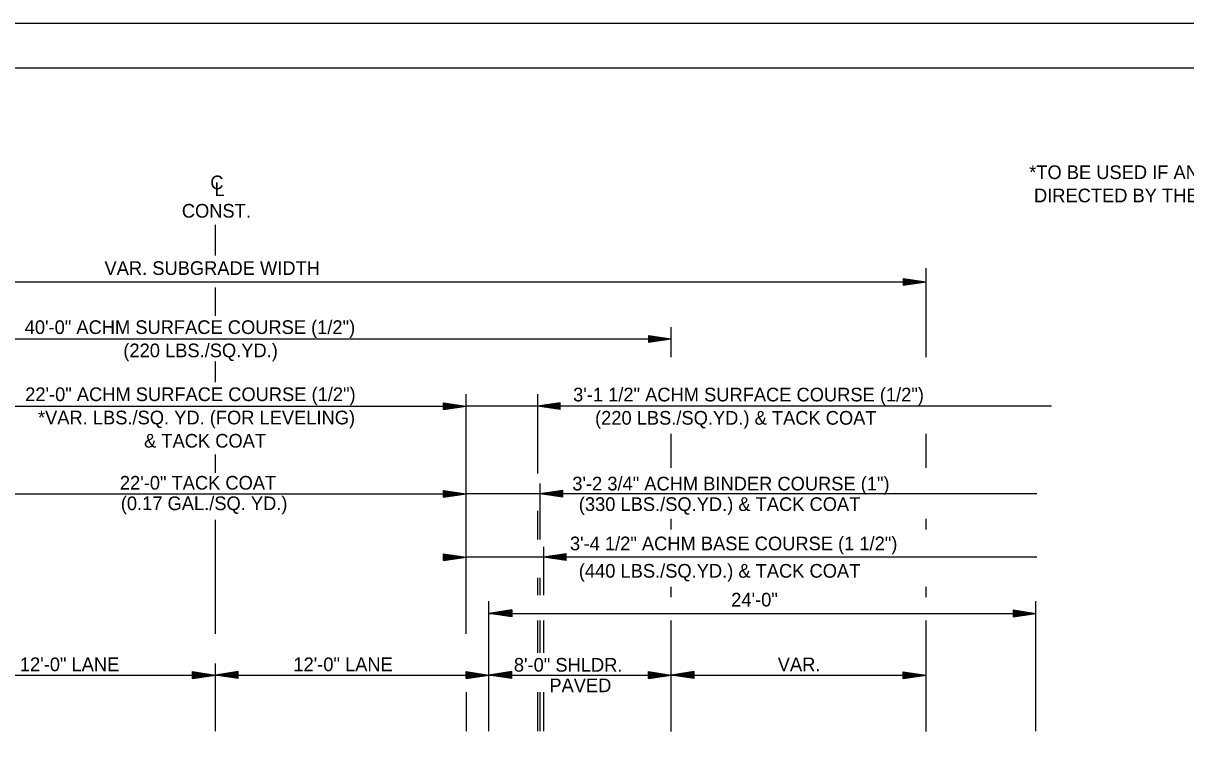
# Model space of a CAD drawing. Extents: x 1371763 to 1372860, y 385599 to 385872.
# Drawn here: x 1372551.5 to 1372602.5, y 385673.9 to 385705.3 of the extents above; entities that cross this region are included whole.
import ezdxf

# ---------------------------------------------------------------- set-up
doc = ezdxf.new("R2010")
doc.units = 0
for name, color, linetype in [('R_Border', 7, 'Continuous'), ('R_Draft', 7, 'Continuous'), ('R_No Plot', 7, 'Continuous')]:
    doc.layers.add(name, color=color, linetype=linetype)

msp = doc.modelspace()

# ---------------------------------------------------------------- linework, layer by layer
at = {"layer": 'R_Border'}
for p, q in [((1372499.208, 385703.307), (1372657.298, 385703.307)), ((1372575.468, 385703.177), (1372575.468, 385703.177)), ((1372575.468, 385703.177), (1372575.468, 385703.177))]:
    msp.add_line(p, q, dxfattribs=at)
at = {"layer": 'R_Draft'}
for p, q in [((1372559.923, 385695.069), (1372559.923, 385696.419)), ((1372591.103, 385690.609), (1372591.103, 385694.519)), ((1372525.346, 385693.919), (1372591.103, 385693.919)), ((1372590.103, 385694.069), (1372591.103, 385693.919)), ((1372590.103, 385694.069), (1372590.103, 385693.769)), ((1372590.103, 385694.044), (1372590.936, 385693.919)), ((1372590.103, 385694.018), (1372590.764, 385693.919)), ((1372590.103, 385693.993), (1372590.598, 385693.919)), ((1372590.103, 385693.967), (1372590.428, 385693.919)), ((1372590.103, 385693.942), (1372590.261, 385693.919)), ((1372590.103, 385693.769), (1372591.103, 385693.919)), ((1372590.103, 385693.87), (1372590.428, 385693.919)), ((1372590.103, 385693.819), (1372590.764, 385693.919)), ((1372590.103, 385693.794), (1372590.936, 385693.919)), ((1372590.103, 385693.844), (1372590.598, 385693.919)), ((1372590.103, 385693.895), (1372590.261, 385693.919)), ((1372559.923, 385692.419), (1372559.923, 385693.669)), ((1372579.918, 385690.609), (1372579.918, 385691.929)), ((1372539.919, 385691.419), (1372579.918, 385691.419)), ((1372578.918, 385691.569), (1372579.918, 385691.419)), ((1372578.918, 385691.569), (1372578.918, 385691.269)), ((1372578.918, 385691.544), (1372579.751, 385691.419)), ((1372578.918, 385691.518), (1372579.579, 385691.419)), ((1372578.918, 385691.493), (1372579.413, 385691.419)), ((1372578.918, 385691.467), (1372579.243, 385691.419)), ((1372578.918, 385691.442), (1372579.076, 385691.419)), ((1372578.918, 385691.269), (1372579.918, 385691.419)), ((1372578.918, 385691.37), (1372579.243, 385691.419)), ((1372578.918, 385691.319), (1372579.579, 385691.419)), ((1372578.918, 385691.294), (1372579.751, 385691.419)), ((1372578.918, 385691.344), (1372579.413, 385691.419)), ((1372578.918, 385691.395), (1372579.076, 385691.419)), ((1372559.923, 385689.51), (1372559.923, 385690.419)), ((1372570.921, 385678.476), (1372570.923, 385688.985)), ((1372574.052, 385688.985), (1372574.052, 385685.506)), ((1372548.923, 385688.463), (1372570.923, 385688.463)), ((1372569.923, 385688.613), (1372570.923, 385688.463)), ((1372569.923, 385688.313), (1372569.923, 385688.613)), ((1372569.923, 385688.588), (1372570.756, 385688.463)), ((1372569.923, 385688.563), (1372570.584, 385688.463)), ((1372569.923, 385688.538), (1372570.417, 385688.463)), ((1372569.923, 385688.512), (1372570.248, 385688.463)), ((1372569.923, 385688.487), (1372570.081, 385688.463)), ((1372569.923, 385688.313), (1372570.923, 385688.463)), ((1372569.923, 385688.415), (1372570.248, 385688.463)), ((1372569.923, 385688.364), (1372570.584, 385688.463)), ((1372569.923, 385688.338), (1372570.756, 385688.463)), ((1372569.923, 385688.389), (1372570.417, 385688.463)), ((1372569.923, 385688.44), (1372570.081, 385688.463)), ((1372596.599, 385688.463), (1372570.923, 385688.463)), ((1372575.052, 385688.613), (1372574.052, 385688.463)), ((1372575.052, 385688.313), (1372574.052, 385688.463)), ((1372575.052, 385688.588), (1372574.219, 385688.463)), ((1372575.052, 385688.338), (1372574.219, 385688.463)), ((1372575.052, 385688.563), (1372574.391, 385688.463)), ((1372575.052, 385688.364), (1372574.391, 385688.463)), ((1372575.052, 385688.538), (1372574.558, 385688.463)), ((1372575.052, 385688.389), (1372574.558, 385688.463)), ((1372575.052, 385688.512), (1372574.727, 385688.463)), ((1372575.052, 385688.415), (1372574.727, 385688.463)), ((1372575.052, 385688.487), (1372574.894, 385688.463)), ((1372575.052, 385688.44), (1372574.894, 385688.463)), ((1372575.052, 385688.313), (1372575.052, 385688.613)), ((1372579.918, 385685.755), (1372579.918, 385687.255)), ((1372591.103, 385685.755), (1372591.103, 385687.255)), ((1372559.919, 385685.538), (1372559.919, 385686.348)), ((1372569.923, 385684.768), (1372570.923, 385684.618)), ((1372569.923, 385684.468), (1372569.923, 385684.768)), ((1372569.923, 385684.743), (1372570.756, 385684.618)), ((1372569.923, 385684.718), (1372570.584, 385684.618)), ((1372569.923, 385684.693), (1372570.417, 385684.618)), ((1372574.162, 385685.069), (1372574.162, 385682.617)), ((1372575.162, 385684.769), (1372574.162, 385684.619)), ((1372575.162, 385684.744), (1372574.329, 385684.619)), ((1372575.162, 385684.718), (1372574.501, 385684.619)), ((1372575.162, 385684.693), (1372574.668, 385684.619)), ((1372575.162, 385684.469), (1372575.162, 385684.769)), ((1372548.923, 385684.618), (1372570.923, 385684.618)), ((1372569.923, 385684.667), (1372570.248, 385684.618)), ((1372569.923, 385684.642), (1372570.081, 385684.618)), ((1372569.923, 385684.468), (1372570.923, 385684.618)), ((1372569.923, 385684.57), (1372570.248, 385684.618)), ((1372569.923, 385684.519), (1372570.584, 385684.618)), ((1372569.923, 385684.493), (1372570.756, 385684.618)), ((1372569.923, 385684.544), (1372570.417, 385684.618)), ((1372569.923, 385684.595), (1372570.081, 385684.618)), ((1372595.964, 385684.619), (1372570.923, 385684.619)), ((1372575.162, 385684.469), (1372574.162, 385684.619)), ((1372575.162, 385684.494), (1372574.329, 385684.619)), ((1372575.162, 385684.519), (1372574.501, 385684.619)), ((1372575.162, 385684.544), (1372574.668, 385684.619)), ((1372575.162, 385684.668), (1372574.837, 385684.619)), ((1372575.162, 385684.57), (1372574.837, 385684.619)), ((1372575.162, 385684.642), (1372575.004, 385684.619)), ((1372575.162, 385684.595), (1372575.004, 385684.619)), ((1372574.052, 385683.868), (1372574.052, 385682.617)), ((1372559.921, 385678.477), (1372559.919, 385683.474)), ((1372579.918, 385683.057), (1372579.918, 385683.523)), ((1372591.103, 385683.057), (1372591.103, 385683.523)), ((1372574.316, 385682.294), (1372574.316, 385680.178)), ((1372569.922, 385681.994), (1372570.922, 385681.844)), ((1372569.922, 385681.694), (1372569.922, 385681.994)), ((1372569.922, 385681.969), (1372570.755, 385681.844)), ((1372569.922, 385681.943), (1372570.583, 385681.844)), ((1372569.922, 385681.918), (1372570.416, 385681.844)), ((1372569.922, 385681.893), (1372570.247, 385681.844)), ((1372569.922, 385681.867), (1372570.08, 385681.844)), ((1372569.922, 385681.694), (1372570.922, 385681.844)), ((1372569.922, 385681.795), (1372570.247, 385681.844)), ((1372569.922, 385681.744), (1372570.583, 385681.844)), ((1372569.922, 385681.719), (1372570.755, 385681.844)), ((1372569.922, 385681.769), (1372570.416, 385681.844)), ((1372569.922, 385681.82), (1372570.08, 385681.844)), ((1372595.964, 385681.844), (1372570.923, 385681.844)), ((1372575.316, 385681.994), (1372574.316, 385681.844)), ((1372575.316, 385681.694), (1372574.316, 385681.844)), ((1372575.316, 385681.969), (1372574.483, 385681.844)), ((1372575.316, 385681.719), (1372574.483, 385681.844)), ((1372575.316, 385681.943), (1372574.655, 385681.844)), ((1372575.316, 385681.744), (1372574.655, 385681.844)), ((1372575.316, 385681.918), (1372574.821, 385681.844)), ((1372575.316, 385681.769), (1372574.821, 385681.844)), ((1372575.316, 385681.893), (1372574.991, 385681.844)), ((1372575.316, 385681.795), (1372574.991, 385681.844)), ((1372575.316, 385681.867), (1372575.158, 385681.844)), ((1372575.316, 385681.82), (1372575.158, 385681.844)), ((1372575.316, 385681.694), (1372575.316, 385681.994)), ((1372574.052, 385680.943), (1372574.052, 385680.178)), ((1372574.162, 385680.943), (1372574.162, 385680.178)), ((1372579.918, 385680.084), (1372579.918, 385680.549)), ((1372591.103, 385680.084), (1372591.103, 385680.549)), ((1372571.92, 385674.207), (1372571.921, 385679.921)), ((1372595.919, 385674.207), (1372595.919, 385679.921)), ((1372572.921, 385679.53), (1372571.921, 385679.38)), ((1372571.921, 385679.38), (1372595.919, 385679.38)), ((1372572.921, 385679.23), (1372571.921, 385679.38)), ((1372572.921, 385679.505), (1372572.088, 385679.38)), ((1372572.921, 385679.255), (1372572.088, 385679.38)), ((1372572.921, 385679.48), (1372572.26, 385679.38)), ((1372572.921, 385679.281), (1372572.26, 385679.38)), ((1372572.921, 385679.455), (1372572.426, 385679.38)), ((1372572.921, 385679.306), (1372572.426, 385679.38)), ((1372572.921, 385679.429), (1372572.596, 385679.38)), ((1372572.921, 385679.331), (1372572.596, 385679.38)), ((1372572.921, 385679.404), (1372572.763, 385679.38)), ((1372572.921, 385679.357), (1372572.763, 385679.38)), ((1372572.921, 385679.53), (1372572.921, 385679.23)), ((1372574.052, 385679.07), (1372574.052, 385677.643)), ((1372574.162, 385679.07), (1372574.162, 385677.643)), ((1372574.316, 385679.07), (1372574.316, 385677.643)), ((1372594.919, 385679.53), (1372595.919, 385679.38)), ((1372594.919, 385679.53), (1372594.919, 385679.23)), ((1372594.919, 385679.505), (1372595.752, 385679.38)), ((1372594.919, 385679.48), (1372595.58, 385679.38)), ((1372594.919, 385679.455), (1372595.413, 385679.38)), ((1372594.919, 385679.429), (1372595.244, 385679.38)), ((1372594.919, 385679.404), (1372595.077, 385679.38)), ((1372594.919, 385679.23), (1372595.919, 385679.38)), ((1372594.919, 385679.331), (1372595.244, 385679.38)), ((1372594.919, 385679.281), (1372595.58, 385679.38)), ((1372594.919, 385679.255), (1372595.752, 385679.38)), ((1372594.919, 385679.306), (1372595.413, 385679.38)), ((1372594.919, 385679.357), (1372595.077, 385679.38)), ((1372579.92, 385674.206), (1372579.92, 385679.069)), ((1372591.103, 385674.205), (1372591.103, 385679.067)), ((1372559.92, 385674.208), (1372559.921, 385677.181)), ((1372547.921, 385676.674), (1372559.921, 385676.674)), ((1372558.921, 385676.824), (1372559.921, 385676.674)), ((1372558.921, 385676.524), (1372558.921, 385676.824)), ((1372558.921, 385676.799), (1372559.754, 385676.674)), ((1372558.921, 385676.773), (1372559.582, 385676.674)), ((1372558.921, 385676.748), (1372559.415, 385676.674)), ((1372558.921, 385676.723), (1372559.246, 385676.674)), ((1372558.921, 385676.697), (1372559.079, 385676.674)), ((1372558.921, 385676.524), (1372559.921, 385676.674)), ((1372558.921, 385676.625), (1372559.246, 385676.674)), ((1372558.921, 385676.574), (1372559.582, 385676.674)), ((1372558.921, 385676.549), (1372559.754, 385676.674)), ((1372558.921, 385676.599), (1372559.415, 385676.674)), ((1372558.921, 385676.65), (1372559.079, 385676.674)), ((1372560.921, 385676.824), (1372559.921, 385676.674)), ((1372559.921, 385676.674), (1372571.921, 385676.674)), ((1372560.921, 385676.524), (1372559.921, 385676.674)), ((1372560.921, 385676.799), (1372560.088, 385676.674)), ((1372560.921, 385676.549), (1372560.088, 385676.674)), ((1372560.921, 385676.773), (1372560.26, 385676.674)), ((1372560.921, 385676.574), (1372560.26, 385676.674)), ((1372560.921, 385676.748), (1372560.426, 385676.674)), ((1372560.921, 385676.599), (1372560.426, 385676.674)), ((1372560.921, 385676.723), (1372560.596, 385676.674)), ((1372560.921, 385676.625), (1372560.596, 385676.674)), ((1372560.921, 385676.697), (1372560.763, 385676.674)), ((1372560.921, 385676.65), (1372560.763, 385676.674)), ((1372560.921, 385676.524), (1372560.921, 385676.824)), ((1372570.921, 385676.824), (1372571.921, 385676.674)), ((1372570.921, 385676.524), (1372570.921, 385676.824)), ((1372570.921, 385676.799), (1372571.754, 385676.674)), ((1372570.921, 385676.773), (1372571.582, 385676.674)), ((1372570.921, 385676.748), (1372571.415, 385676.674)), ((1372570.921, 385676.723), (1372571.246, 385676.674)), ((1372570.921, 385676.697), (1372571.079, 385676.674)), ((1372570.921, 385676.524), (1372571.921, 385676.674)), ((1372570.921, 385676.625), (1372571.246, 385676.674)), ((1372570.921, 385676.574), (1372571.582, 385676.674)), ((1372570.921, 385676.549), (1372571.754, 385676.674)), ((1372570.921, 385676.599), (1372571.415, 385676.674)), ((1372570.921, 385676.65), (1372571.079, 385676.674)), ((1372572.92, 385676.824), (1372571.92, 385676.674)), ((1372572.92, 385676.524), (1372571.92, 385676.674)), ((1372571.92, 385676.674), (1372579.92, 385676.674)), ((1372572.92, 385676.799), (1372572.087, 385676.674)), ((1372572.92, 385676.549), (1372572.087, 385676.674)), ((1372572.92, 385676.773), (1372572.259, 385676.674)), ((1372572.92, 385676.574), (1372572.259, 385676.674)), ((1372572.92, 385676.748), (1372572.425, 385676.674)), ((1372572.92, 385676.599), (1372572.425, 385676.674)), ((1372572.92, 385676.723), (1372572.595, 385676.674)), ((1372572.92, 385676.625), (1372572.595, 385676.674)), ((1372572.92, 385676.697), (1372572.762, 385676.674)), ((1372572.92, 385676.65), (1372572.762, 385676.674)), ((1372572.92, 385676.524), (1372572.92, 385676.824)), ((1372578.92, 385676.824), (1372579.92, 385676.674)), ((1372578.92, 385676.524), (1372578.92, 385676.824)), ((1372578.92, 385676.799), (1372579.753, 385676.674)), ((1372578.92, 385676.773), (1372579.581, 385676.674)), ((1372578.92, 385676.748), (1372579.414, 385676.674)), ((1372578.92, 385676.723), (1372579.245, 385676.674)), ((1372578.92, 385676.697), (1372579.078, 385676.674)), ((1372578.92, 385676.524), (1372579.92, 385676.674)), ((1372578.92, 385676.625), (1372579.245, 385676.674)), ((1372578.92, 385676.574), (1372579.581, 385676.674)), ((1372578.92, 385676.549), (1372579.753, 385676.674)), ((1372578.92, 385676.599), (1372579.414, 385676.674)), ((1372578.92, 385676.65), (1372579.078, 385676.674)), ((1372580.92, 385676.824), (1372579.92, 385676.674)), ((1372580.92, 385676.524), (1372579.92, 385676.674)), ((1372579.92, 385676.674), (1372591.103, 385676.673)), ((1372580.92, 385676.799), (1372580.087, 385676.674)), ((1372580.92, 385676.549), (1372580.087, 385676.674)), ((1372580.92, 385676.773), (1372580.259, 385676.674)), ((1372580.92, 385676.574), (1372580.259, 385676.674)), ((1372580.92, 385676.748), (1372580.425, 385676.674)), ((1372580.92, 385676.599), (1372580.425, 385676.674)), ((1372580.92, 385676.723), (1372580.595, 385676.674)), ((1372580.92, 385676.625), (1372580.595, 385676.674)), ((1372580.92, 385676.697), (1372580.762, 385676.674)), ((1372580.92, 385676.65), (1372580.762, 385676.674)), ((1372580.92, 385676.524), (1372580.92, 385676.824)), ((1372590.103, 385676.823), (1372591.103, 385676.673)), ((1372590.103, 385676.523), (1372590.103, 385676.823)), ((1372590.103, 385676.798), (1372590.936, 385676.673)), ((1372590.103, 385676.772), (1372590.764, 385676.673)), ((1372590.103, 385676.747), (1372590.597, 385676.673)), ((1372590.103, 385676.722), (1372590.428, 385676.673)), ((1372590.103, 385676.696), (1372590.261, 385676.673)), ((1372590.103, 385676.523), (1372591.103, 385676.673)), ((1372590.103, 385676.624), (1372590.428, 385676.673)), ((1372590.103, 385676.573), (1372590.764, 385676.673)), ((1372590.103, 385676.548), (1372590.936, 385676.673)), ((1372590.103, 385676.598), (1372590.597, 385676.673)), ((1372590.103, 385676.649), (1372590.261, 385676.673)), ((1372570.921, 385675.924), (1372570.921, 385674.207)), ((1372574.052, 385675.924), (1372574.052, 385674.207)), ((1372574.162, 385675.924), (1372574.162, 385674.207)), ((1372574.316, 385675.924), (1372574.316, 385674.207))]:
    msp.add_line(p, q, dxfattribs=at)
at = {"layer": 'R_No Plot'}
msp.add_line((1372493.007, 385705.254), (1372659.674, 385705.254), dxfattribs=at)
for points in [[(1372493.004, 385705.254), (1372659.674, 385705.254), (1372659.674, 385598.585), (1372493.004, 385598.585)], [(1372616.168, 385703.307), (1372625.978, 385703.307), (1372625.978, 385698.367), (1372634.034, 385698.367), (1372645.634, 385698.367), (1372645.634, 385682.032), (1372657.238, 385682.032), (1372657.298, 385600.577), (1372499.208, 385600.577), (1372499.208, 385703.307)]]:
    msp.add_lwpolyline(points, close=True, dxfattribs=at)

# ---------------------------------------------------------------- texts
at = {"layer": 'R_Draft'}
for s, rotation, p in [('*TO BE USED IF AND WHERE ', 360, (1372595.626, 385698.423)), ('C', 360, (1372559.698, 385697.975)), ('L', 360, (1372559.884, 385697.675)), ('DIRECTED BY THE ENGINEER', 360, (1372595.836, 385697.403)), ('CONST.', 360, (1372558.449, 385696.731)), ('VAR. SUBGRADE WIDTH', 360, (1372555.057, 385694.219)), ('40\'-0" ACHM SURFACE COURSE (1/2")', 360, (1372551.556, 385691.629)), ('(220 LBS./SQ.YD.)', 360, (1372555.883, 385690.609)), ('22\'-0" ACHM SURFACE COURSE (1/2")', 360, (1372551.576, 385688.687)), ('3\'-1 1/2" ACHM SURFACE COURSE (1/2")', 0, (1372575.617, 385688.673)), ('*VAR. LBS./SQ. YD. (FOR LEVELING)', 360, (1372552.138, 385687.667)), ('(220 LBS./SQ.YD.) & TACK COAT', 0, (1372576.578, 385687.653)), ('& TACK COAT', 360, (1372556.794, 385686.647)), ('22\'-0" TACK COAT', 360, (1372555.731, 385684.805)), ('3\'-2 3/4" ACHM BINDER COURSE (1")', 0, (1372575.58, 385684.769)), ('(0.17 GAL./SQ. YD.)', 360, (1372555.771, 385683.905)), ('(330 LBS./SQ.YD.) & TACK COAT', 0, (1372575.866, 385683.869)), ('3\'-4 1/2" ACHM BASE COURSE (1 1/2")', 360, (1372575.476, 385682.144)), ('(440 LBS./SQ.YD.) & TACK COAT', 360, (1372575.866, 385680.944)), ('12\'-0" LANE', 360, (1372551.343, 385676.845)), ('12\'-0" LANE', 360, (1372563.343, 385676.845)), ('8\'-0" SHLDR.', 360, (1372573.017, 385676.823)), ('VAR.', 360, (1372584.594, 385676.844)), ('PAVED', 360, (1372574.573, 385675.923))]:
    msp.add_text(s, height=0.6, rotation=rotation, dxfattribs=at).set_placement(p)
msp.add_text('24\'-0"', height=0.6, dxfattribs=at).set_placement((1372582.553, 385679.68))

doc.saveas('drawing.dxf')
